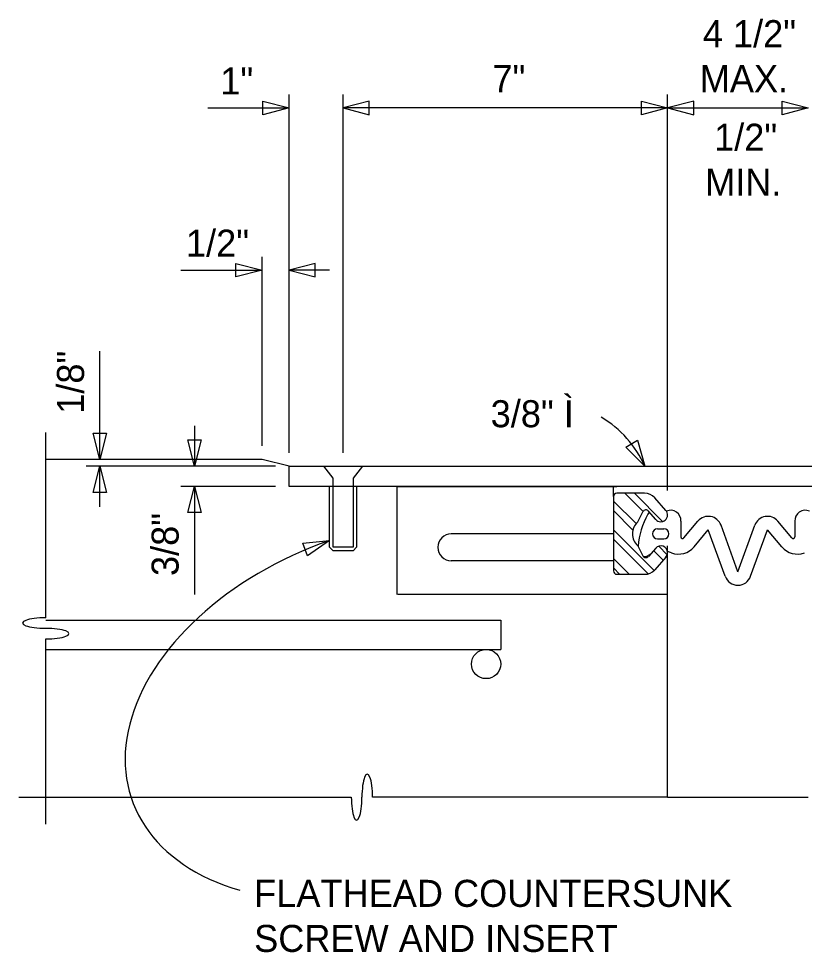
# Model space of a CAD drawing. Extents: x 19590 to 20151, y 19944 to 20103.
# Drawn here: x 19877.36 to 19890.8, y 20053.82 to 20069.79 of the extents above; entities that cross this region are included whole.
import ezdxf

# ---------------------------------------------------------------- set-up
doc = ezdxf.new("R2010")
doc.units = 0
for name, color, linetype in [('B-O', 7, 'Continuous'), ('Default', 7, 'Continuous'), ('DETAIL_PR', 7, 'Continuous'), ('DETAIL_TEXT_DIMEN_PR', 7, 'Continuous'), ('Level 1', 7, 'Continuous'), ('Sheet_Label_Str_Wt0', 7, 'Continuous')]:
    doc.layers.add(name, color=color, linetype=linetype)

# ---------------------------------------------------------------- blocks, each defined once
blk = doc.blocks.new('_X7')
at = {"layer": 'Default'}
for p, q in [((8.051, 16.889), (8.594, 17.433)), ((8.426, 17.08), (8.778, 17.433)), ((8.56, 16.847), (8.995, 17.282)), ((8.622, 16.724), (8.995, 17.098)), ((8.213, 15.947), (8.995, 16.729)), ((7.96, 16.247), (8.125, 16.412)), ((8.329, 15.879), (8.995, 16.545)), ((8.04, 16.142), (8.224, 16.326)), ((8.689, 15.87), (8.995, 16.177)), ((8.873, 15.87), (8.995, 15.993))]:
    blk.add_line(p, q, dxfattribs=at)

msp = doc.modelspace()

# ---------------------------------------------------------------- linework, layer by layer
at = {"layer": 'B-O'}
msp.add_line((19883.835, 20061.786), (19887.593, 20061.786), dxfattribs=at)
msp.add_line((19883.835, 20061.786), (19887.593, 20061.786), dxfattribs=at)
at = {"layer": 'DETAIL_PR'}
for p, q in [((19881.523, 20062.248), (19877.823, 20062.248)), ((19881.523, 20062.248), (19877.823, 20062.248)), ((19881.985, 20062.133), (19881.523, 20062.248)), ((19881.985, 20062.133), (19881.523, 20062.248)), ((19881.985, 20061.786), (19881.985, 20062.133)), ((19881.985, 20062.133), (19898.519, 20062.133)), ((19881.985, 20061.786), (19881.985, 20062.133)), ((19881.985, 20062.133), (19898.519, 20062.133)), ((19882.737, 20061.926), (19882.578, 20062.133)), ((19882.578, 20062.133), (19883.242, 20062.133)), ((19882.737, 20061.926), (19882.578, 20062.133)), ((19882.578, 20062.133), (19883.242, 20062.133)), ((19883.242, 20062.133), (19883.083, 20061.926)), ((19883.242, 20062.133), (19883.083, 20061.926)), ((19882.737, 20060.745), (19882.737, 20061.926)), ((19882.737, 20060.745), (19882.737, 20061.926)), ((19883.083, 20061.926), (19883.083, 20060.745)), ((19883.083, 20061.926), (19883.083, 20060.745)), ((19898.635, 20061.786), (19881.985, 20061.786)), ((19898.635, 20061.786), (19881.985, 20061.786)), ((19882.679, 20060.745), (19882.679, 20061.786)), ((19882.679, 20060.745), (19882.679, 20061.786)), ((19883.141, 20061.786), (19883.141, 20060.745)), ((19883.141, 20061.786), (19883.141, 20060.745)), ((19883.835, 20059.936), (19883.835, 20061.786)), ((19883.835, 20059.936), (19883.835, 20061.786)), ((19887.535, 20061.612), (19887.535, 20061.786)), ((19887.535, 20061.612), (19887.535, 20061.786)), ((19887.535, 20061.612), (19887.535, 20060.976)), ((19887.535, 20061.612), (19887.535, 20060.976)), ((19888.067, 20061.67), (19887.593, 20061.67)), ((19888.067, 20061.67), (19887.593, 20061.67)), ((19888.431, 20061.376), (19888.24, 20061.592)), ((19888.431, 20061.376), (19888.24, 20061.592)), ((19888.258, 20061.223), (19888.133, 20061.364)), ((19888.258, 20061.223), (19888.133, 20061.364)), ((19887.951, 20061.18), (19888.038, 20061.352)), ((19887.951, 20061.18), (19888.038, 20061.352)), ((19888.688, 20061.193), (19888.688, 20060.924)), ((19888.688, 20061.193), (19888.688, 20060.924)), ((19888.739, 20060.905), (19888.98, 20061.192)), ((19888.739, 20060.905), (19888.98, 20061.192)), ((19890.588, 20060.905), (19890.347, 20061.192)), ((19890.588, 20060.905), (19890.347, 20061.192)), ((19890.639, 20061.193), (19890.639, 20060.924)), ((19890.639, 20061.193), (19890.639, 20060.924)), ((19888.29, 20061.063), (19888.395, 20061.063)), ((19888.29, 20061.063), (19888.395, 20061.063)), ((19888.913, 20060.753), (19889.157, 20061.044)), ((19888.913, 20060.753), (19889.157, 20061.044)), ((19889.446, 20060.249), (19889.157, 20061.044)), ((19889.446, 20060.249), (19889.157, 20061.044)), ((19889.664, 20060.328), (19889.375, 20061.123)), ((19889.664, 20060.328), (19889.375, 20061.123)), ((19889.664, 20060.328), (19889.953, 20061.123)), ((19889.664, 20060.328), (19889.953, 20061.123)), ((19889.881, 20060.249), (19890.17, 20061.044)), ((19889.881, 20060.249), (19890.17, 20061.044)), ((19890.414, 20060.753), (19890.17, 20061.044)), ((19890.414, 20060.753), (19890.17, 20061.044)), ((19887.535, 20060.976), (19884.76, 20060.976)), ((19887.535, 20060.976), (19884.76, 20060.976)), ((19887.535, 20060.976), (19887.535, 20060.514)), ((19887.535, 20060.976), (19887.535, 20060.514)), ((19888.29, 20060.89), (19888.395, 20060.89)), ((19888.29, 20060.89), (19888.395, 20060.89)), ((19882.679, 20060.745), (19882.737, 20060.687)), ((19882.679, 20060.745), (19882.737, 20060.687)), ((19883.083, 20060.745), (19882.737, 20060.745)), ((19883.083, 20060.745), (19882.737, 20060.745)), ((19883.141, 20060.745), (19883.083, 20060.687)), ((19883.141, 20060.745), (19883.083, 20060.687)), ((19887.951, 20060.773), (19888.038, 20060.601)), ((19887.951, 20060.773), (19888.038, 20060.601)), ((19888.258, 20060.73), (19888.133, 20060.589)), ((19888.258, 20060.73), (19888.133, 20060.589)), ((19888.46, 20056.47), (19888.46, 20060.769)), ((19888.46, 20056.47), (19888.46, 20060.769)), ((19883.083, 20060.687), (19882.737, 20060.687)), ((19883.083, 20060.687), (19882.737, 20060.687)), ((19888.168, 20060.629), (19888.126, 20060.604)), ((19888.168, 20060.629), (19888.126, 20060.604)), ((19888.431, 20060.577), (19888.24, 20060.361)), ((19888.431, 20060.577), (19888.24, 20060.361)), ((19888.528, 20060.65), (19888.458, 20060.676)), ((19888.528, 20060.65), (19888.458, 20060.676)), ((19887.535, 20060.514), (19884.76, 20060.514)), ((19887.535, 20060.514), (19884.76, 20060.514)), ((19887.535, 20060.514), (19887.535, 20060.341)), ((19887.535, 20060.514), (19887.535, 20060.341)), ((19887.593, 20060.283), (19888.067, 20060.283)), ((19887.593, 20060.283), (19888.067, 20060.283)), ((19888.46, 20059.936), (19883.847, 20059.936)), ((19888.46, 20059.936), (19883.847, 20059.936)), ((19877.823, 20059.498), (19885.605, 20059.498)), ((19877.823, 20059.498), (19885.605, 20059.498)), ((19885.605, 20059.498), (19885.605, 20058.998)), ((19885.605, 20059.498), (19885.605, 20058.998)), ((19877.823, 20058.998), (19885.605, 20058.998)), ((19877.823, 20058.998), (19885.605, 20058.998))]:
    msp.add_line(p, q, dxfattribs=at)
msp.add_circle((19885.355, 20058.748), 0.25, dxfattribs=at)
msp.add_circle((19885.355, 20058.748), 0.25, dxfattribs=at)
for centre, radius, start, end in [((19887.593, 20061.612), 0.0578, 90, 180), ((19887.593, 20061.612), 0.0578, 90, 180), ((19888.067, 20061.439), 0.231, 41.462, 90), ((19888.067, 20061.439), 0.231, 41.462, 90), ((19888.09, 20061.326), 0.0578, 41.462, 153.1909), ((19888.09, 20061.326), 0.0578, 41.462, 153.1909), ((19888.344, 20061.299), 0.116, 221.462, 41.462), ((19888.344, 20061.299), 0.116, 221.462, 41.462), ((19888.515, 20061.206), 0.173, 355.6455, 115.2375), ((19888.515, 20061.206), 0.173, 355.6455, 115.2375), ((19890.812, 20061.206), 0.173, 64.7625, 184.3545), ((19890.812, 20061.206), 0.173, 64.7625, 184.3545), ((19889.338, 20060.643), 1.388, 151.2528, 175.0143), ((19889.338, 20060.643), 1.388, 151.2528, 175.0143), ((19888.172, 20061.283), 0.0578, 106.6655, 151.2528), ((19888.172, 20061.283), 0.0578, 106.6655, 151.2528), ((19889.157, 20061.044), 0.231, 19.9948, 140), ((19889.157, 20061.044), 0.231, 19.9948, 140), ((19890.17, 20061.044), 0.231, 40, 160.0052), ((19890.17, 20061.044), 0.231, 40, 160.0052), ((19888.129, 20060.976), 0.27, 131.1121, 228.8879), ((19888.129, 20060.976), 0.27, 131.1121, 228.8879), ((19888.29, 20060.976), 0.0867, 90, 270), ((19888.29, 20060.976), 0.0867, 90, 270), ((19888.395, 20060.976), 0.0867, 270, 90), ((19888.395, 20060.976), 0.0867, 270, 90), ((19884.76, 20060.745), 0.231, 90, 270), ((19884.76, 20060.745), 0.231, 90, 270), ((19888.717, 20060.924), 0.0289, 180, 320), ((19888.717, 20060.924), 0.0289, 180, 320), ((19890.61, 20060.924), 0.0289, 220, 0), ((19890.61, 20060.924), 0.0289, 220, 0), ((19888.344, 20060.654), 0.116, 0, 138.538), ((19888.344, 20060.654), 0.116, 0, 138.538), ((19888.648, 20060.976), 0.347, 249.847, 320), ((19888.648, 20060.976), 0.347, 249.847, 320), ((19890.68, 20060.976), 0.347, 220, 290.153), ((19890.68, 20060.976), 0.347, 220, 290.153), ((19888.09, 20060.627), 0.0578, 206.8091, 318.538), ((19888.09, 20060.627), 0.0578, 206.8091, 318.538), ((19888.068, 20060.704), 0.116, 258.4931, 300), ((19888.068, 20060.704), 0.116, 258.4931, 300), ((19888.344, 20060.654), 0.116, 318.538, 0), ((19888.344, 20060.654), 0.116, 318.538, 0), ((19887.593, 20060.341), 0.0578, 180, 270), ((19887.593, 20060.341), 0.0578, 180, 270), ((19888.067, 20060.514), 0.231, 270, 318.538), ((19888.067, 20060.514), 0.231, 270, 318.538), ((19889.664, 20060.328), 0.231, 200, 340), ((19889.664, 20060.328), 0.231, 200, 340)]:
    msp.add_arc(centre, radius, start, end, dxfattribs=at)
for centre, major_axis, ratio, start_param, end_param in [((19877.823, 20059.45), (0.395, 0), 0.230204, 1.570796, 4.712389), ((19877.823, 20059.45), (0.395, 0), 0.230204, 1.570796, 4.712389), ((19877.823, 20059.268), (0.395, 0), 0.230206, 4.712389, 7.853982), ((19877.823, 20059.268), (0.395, 0), 0.230206, 4.712389, 7.853982), ((19883.323, 20056.47), (0, -0.395), 0.230204, 1.570796, 4.712389), ((19883.323, 20056.47), (0, -0.395), 0.230204, 1.570796, 4.712389), ((19883.141, 20056.47), (0, -0.395), 0.230206, 4.712389, 7.853982), ((19883.141, 20056.47), (0, -0.395), 0.230206, 4.712389, 7.853982)]:
    msp.add_ellipse(centre, major_axis=major_axis, ratio=ratio, start_param=start_param, end_param=end_param, dxfattribs=at)
at = {"layer": 'DETAIL_TEXT_DIMEN_PR'}
for p, q in [((19881.985, 20062.364), (19881.985, 20068.492)), ((19881.985, 20062.364), (19881.985, 20068.492)), ((19882.91, 20062.364), (19882.91, 20068.492)), ((19882.91, 20062.364), (19882.91, 20068.492)), ((19888.46, 20061.717), (19888.46, 20068.492)), ((19888.46, 20061.717), (19888.46, 20068.492)), ((19881.537, 20068.145), (19881.537, 20068.376)), ((19881.537, 20068.376), (19881.985, 20068.261)), ((19881.537, 20068.145), (19881.537, 20068.376)), ((19881.537, 20068.376), (19881.985, 20068.261)), ((19881.985, 20068.261), (19881.537, 20068.145)), ((19881.985, 20068.261), (19881.537, 20068.145)), ((19883.358, 20068.376), (19882.91, 20068.261)), ((19883.358, 20068.376), (19882.91, 20068.261)), ((19888.46, 20068.261), (19882.91, 20068.261)), ((19882.91, 20068.261), (19883.358, 20068.145)), ((19888.46, 20068.261), (19882.91, 20068.261)), ((19882.91, 20068.261), (19883.358, 20068.145)), ((19883.358, 20068.145), (19883.358, 20068.376)), ((19883.358, 20068.145), (19883.358, 20068.376)), ((19888.012, 20068.145), (19888.012, 20068.376)), ((19888.012, 20068.376), (19888.46, 20068.261)), ((19888.012, 20068.145), (19888.012, 20068.376)), ((19888.012, 20068.376), (19888.46, 20068.261)), ((19888.46, 20068.261), (19888.012, 20068.145)), ((19888.46, 20068.261), (19888.012, 20068.145)), ((19888.908, 20068.376), (19888.46, 20068.261)), ((19888.908, 20068.376), (19888.46, 20068.261)), ((19888.46, 20068.261), (19890.867, 20068.261)), ((19888.46, 20068.261), (19888.908, 20068.145)), ((19888.46, 20068.261), (19890.867, 20068.261)), ((19888.46, 20068.261), (19888.908, 20068.145)), ((19888.908, 20068.145), (19888.908, 20068.376)), ((19888.908, 20068.145), (19888.908, 20068.376)), ((19890.419, 20068.145), (19890.419, 20068.376)), ((19890.419, 20068.376), (19890.867, 20068.261)), ((19890.419, 20068.145), (19890.419, 20068.376)), ((19890.419, 20068.376), (19890.867, 20068.261)), ((19890.867, 20068.261), (19890.419, 20068.145)), ((19890.867, 20068.261), (19890.419, 20068.145)), ((19881.523, 20062.48), (19881.523, 20065.717)), ((19881.523, 20062.48), (19881.523, 20065.717)), ((19881.075, 20065.37), (19881.075, 20065.601)), ((19881.075, 20065.601), (19881.523, 20065.486)), ((19881.075, 20065.37), (19881.075, 20065.601)), ((19881.075, 20065.601), (19881.523, 20065.486)), ((19882.433, 20065.601), (19881.985, 20065.486)), ((19882.433, 20065.601), (19881.985, 20065.486)), ((19882.433, 20065.37), (19882.433, 20065.601)), ((19882.433, 20065.37), (19882.433, 20065.601)), ((19881.523, 20065.486), (19881.075, 20065.37)), ((19881.523, 20065.486), (19881.075, 20065.37)), ((19881.985, 20065.486), (19882.433, 20065.37)), ((19881.985, 20065.486), (19882.433, 20065.37)), ((19877.823, 20059.541), (19877.823, 20062.711)), ((19877.823, 20059.541), (19877.823, 20062.711)), ((19878.632, 20062.696), (19878.863, 20062.696)), ((19878.748, 20062.248), (19878.632, 20062.696)), ((19878.632, 20062.696), (19878.863, 20062.696)), ((19878.748, 20062.248), (19878.632, 20062.696)), ((19878.863, 20062.696), (19878.748, 20062.248)), ((19878.863, 20062.696), (19878.748, 20062.248)), ((19880.251, 20062.581), (19880.482, 20062.581)), ((19880.366, 20062.133), (19880.251, 20062.581)), ((19880.251, 20062.581), (19880.482, 20062.581)), ((19880.366, 20062.133), (19880.251, 20062.581)), ((19880.482, 20062.581), (19880.366, 20062.133)), ((19880.482, 20062.581), (19880.366, 20062.133)), ((19887.747, 20062.461), (19887.947, 20062.578)), ((19887.747, 20062.461), (19887.947, 20062.578)), ((19887.947, 20062.578), (19888.073, 20062.133)), ((19887.947, 20062.578), (19888.073, 20062.133)), ((19888.073, 20062.133), (19887.747, 20062.461)), ((19888.073, 20062.133), (19887.747, 20062.461)), ((19881.754, 20062.133), (19878.516, 20062.133)), ((19881.754, 20062.133), (19878.516, 20062.133)), ((19878.632, 20061.685), (19878.748, 20062.133)), ((19878.632, 20061.685), (19878.748, 20062.133)), ((19878.748, 20062.133), (19878.863, 20061.685)), ((19878.748, 20062.133), (19878.863, 20061.685)), ((19878.863, 20061.685), (19878.632, 20061.685)), ((19878.863, 20061.685), (19878.632, 20061.685)), ((19881.754, 20061.786), (19880.135, 20061.786)), ((19881.754, 20061.786), (19880.135, 20061.786)), ((19880.251, 20061.338), (19880.366, 20061.786)), ((19880.251, 20061.338), (19880.366, 20061.786)), ((19880.366, 20061.786), (19880.482, 20061.338)), ((19880.366, 20061.786), (19880.482, 20061.338)), ((19880.482, 20061.338), (19880.251, 20061.338)), ((19880.482, 20061.338), (19880.251, 20061.338)), ((19882.219, 20060.816), (19882.679, 20060.862)), ((19882.219, 20060.816), (19882.679, 20060.862)), ((19882.298, 20060.599), (19882.219, 20060.816)), ((19882.298, 20060.599), (19882.219, 20060.816)), ((19882.679, 20060.862), (19882.298, 20060.599)), ((19882.679, 20060.862), (19882.298, 20060.599)), ((19877.823, 20056.008), (19877.823, 20059.177)), ((19877.823, 20056.008), (19877.823, 20059.177)), ((19877.36, 20056.47), (19883.05, 20056.47)), ((19877.36, 20056.47), (19883.05, 20056.47)), ((19888.46, 20056.47), (19883.414, 20056.47)), ((19888.46, 20056.47), (19883.414, 20056.47))]:
    msp.add_line(p, q, dxfattribs=at)
at = {"layer": 'Level 1'}
for p, q in [((19880.598, 20068.261), (19881.985, 20068.261)), ((19880.598, 20068.261), (19881.985, 20068.261)), ((19880.135, 20065.486), (19881.523, 20065.486)), ((19880.135, 20065.486), (19881.523, 20065.486)), ((19882.679, 20065.486), (19881.985, 20065.486)), ((19882.679, 20065.486), (19881.985, 20065.486)), ((19878.748, 20062.248), (19878.748, 20064.098)), ((19878.748, 20062.248), (19878.748, 20064.098)), ((19880.366, 20062.826), (19880.366, 20062.133)), ((19880.366, 20062.826), (19880.366, 20062.133)), ((19878.748, 20061.439), (19878.748, 20062.133)), ((19878.748, 20061.439), (19878.748, 20062.133)), ((19880.366, 20061.786), (19880.366, 20059.936)), ((19880.366, 20061.786), (19880.366, 20059.936)), ((19888.46, 20056.47), (19890.867, 20056.47)), ((19888.46, 20056.47), (19890.867, 20056.47))]:
    msp.add_line(p, q, dxfattribs=at)
msp.add_arc((19886.368, 20061.365), 1.87, 24.225, 59.1642, dxfattribs=at)
msp.add_arc((19886.368, 20061.365), 1.87, 24.225, 59.1642, dxfattribs=at)
msp.add_ellipse((19883.693, 20057.97), major_axis=(4.397, 1.542), ratio=0.657723, start_param=1.570796, end_param=3.885568, dxfattribs=at)
msp.add_ellipse((19883.693, 20057.97), major_axis=(4.397, 1.542), ratio=0.657723, start_param=1.570796, end_param=3.885568, dxfattribs=at)

# ---------------------------------------------------------------- block references
at = {"layer": 'DETAIL_PR', "xscale": 0.8880107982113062, "yscale": -0.8880107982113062, "rotation": 180}
msp.add_blockref('_X7', (19895.523, 20046.19), dxfattribs=at)
msp.add_blockref('_X7', (19895.523, 20046.19), dxfattribs=at)

# ---------------------------------------------------------------- texts
at = {"layer": 'DETAIL_TEXT_DIMEN_PR'}
for s, p in [('4 1/2"', (19889.063, 20069.301)), ('4 1/2"', (19889.063, 20069.301)), ('1"', (19880.809, 20068.492)), ('1"', (19880.809, 20068.492)), ('7"', (19885.464, 20068.531)), ('7"', (19885.464, 20068.531)), ('MAX.', (19889.01, 20068.531)), ('MAX.', (19889.01, 20068.531)), ('1/2"', (19889.256, 20067.529)), ('1/2"', (19889.256, 20067.529)), ('MIN.', (19889.102, 20066.758)), ('MIN.', (19889.102, 20066.758)), ('1/2"', (19880.222, 20065.717)), ('1/2"', (19880.222, 20065.717)), ('FLATHEAD COUNTERSUNK', (19881.388, 20054.594)), ('FLATHEAD COUNTERSUNK', (19881.388, 20054.594)), ('SCREW AND INSERT', (19881.388, 20053.823)), ('SCREW AND INSERT', (19881.388, 20053.823))]:
    msp.add_text(s, height=0.4625, dxfattribs=at).set_placement(p)
for s, p in [('1/8"', (19878.478, 20063.029)), ('1/8"', (19878.478, 20063.029)), ('3/8"', (19880.096, 20060.254)), ('3/8"', (19880.096, 20060.254))]:
    msp.add_text(s, height=0.4625, rotation=90, dxfattribs=at).set_placement(p)
at = {"layer": 'Sheet_Label_Str_Wt0'}
msp.add_text('3/8" Ì', height=0.4625, dxfattribs=at).set_placement((19885.434, 20062.799))
msp.add_text('3/8" Ì', height=0.4625, dxfattribs=at).set_placement((19885.434, 20062.799))

doc.saveas('drawing.dxf')
